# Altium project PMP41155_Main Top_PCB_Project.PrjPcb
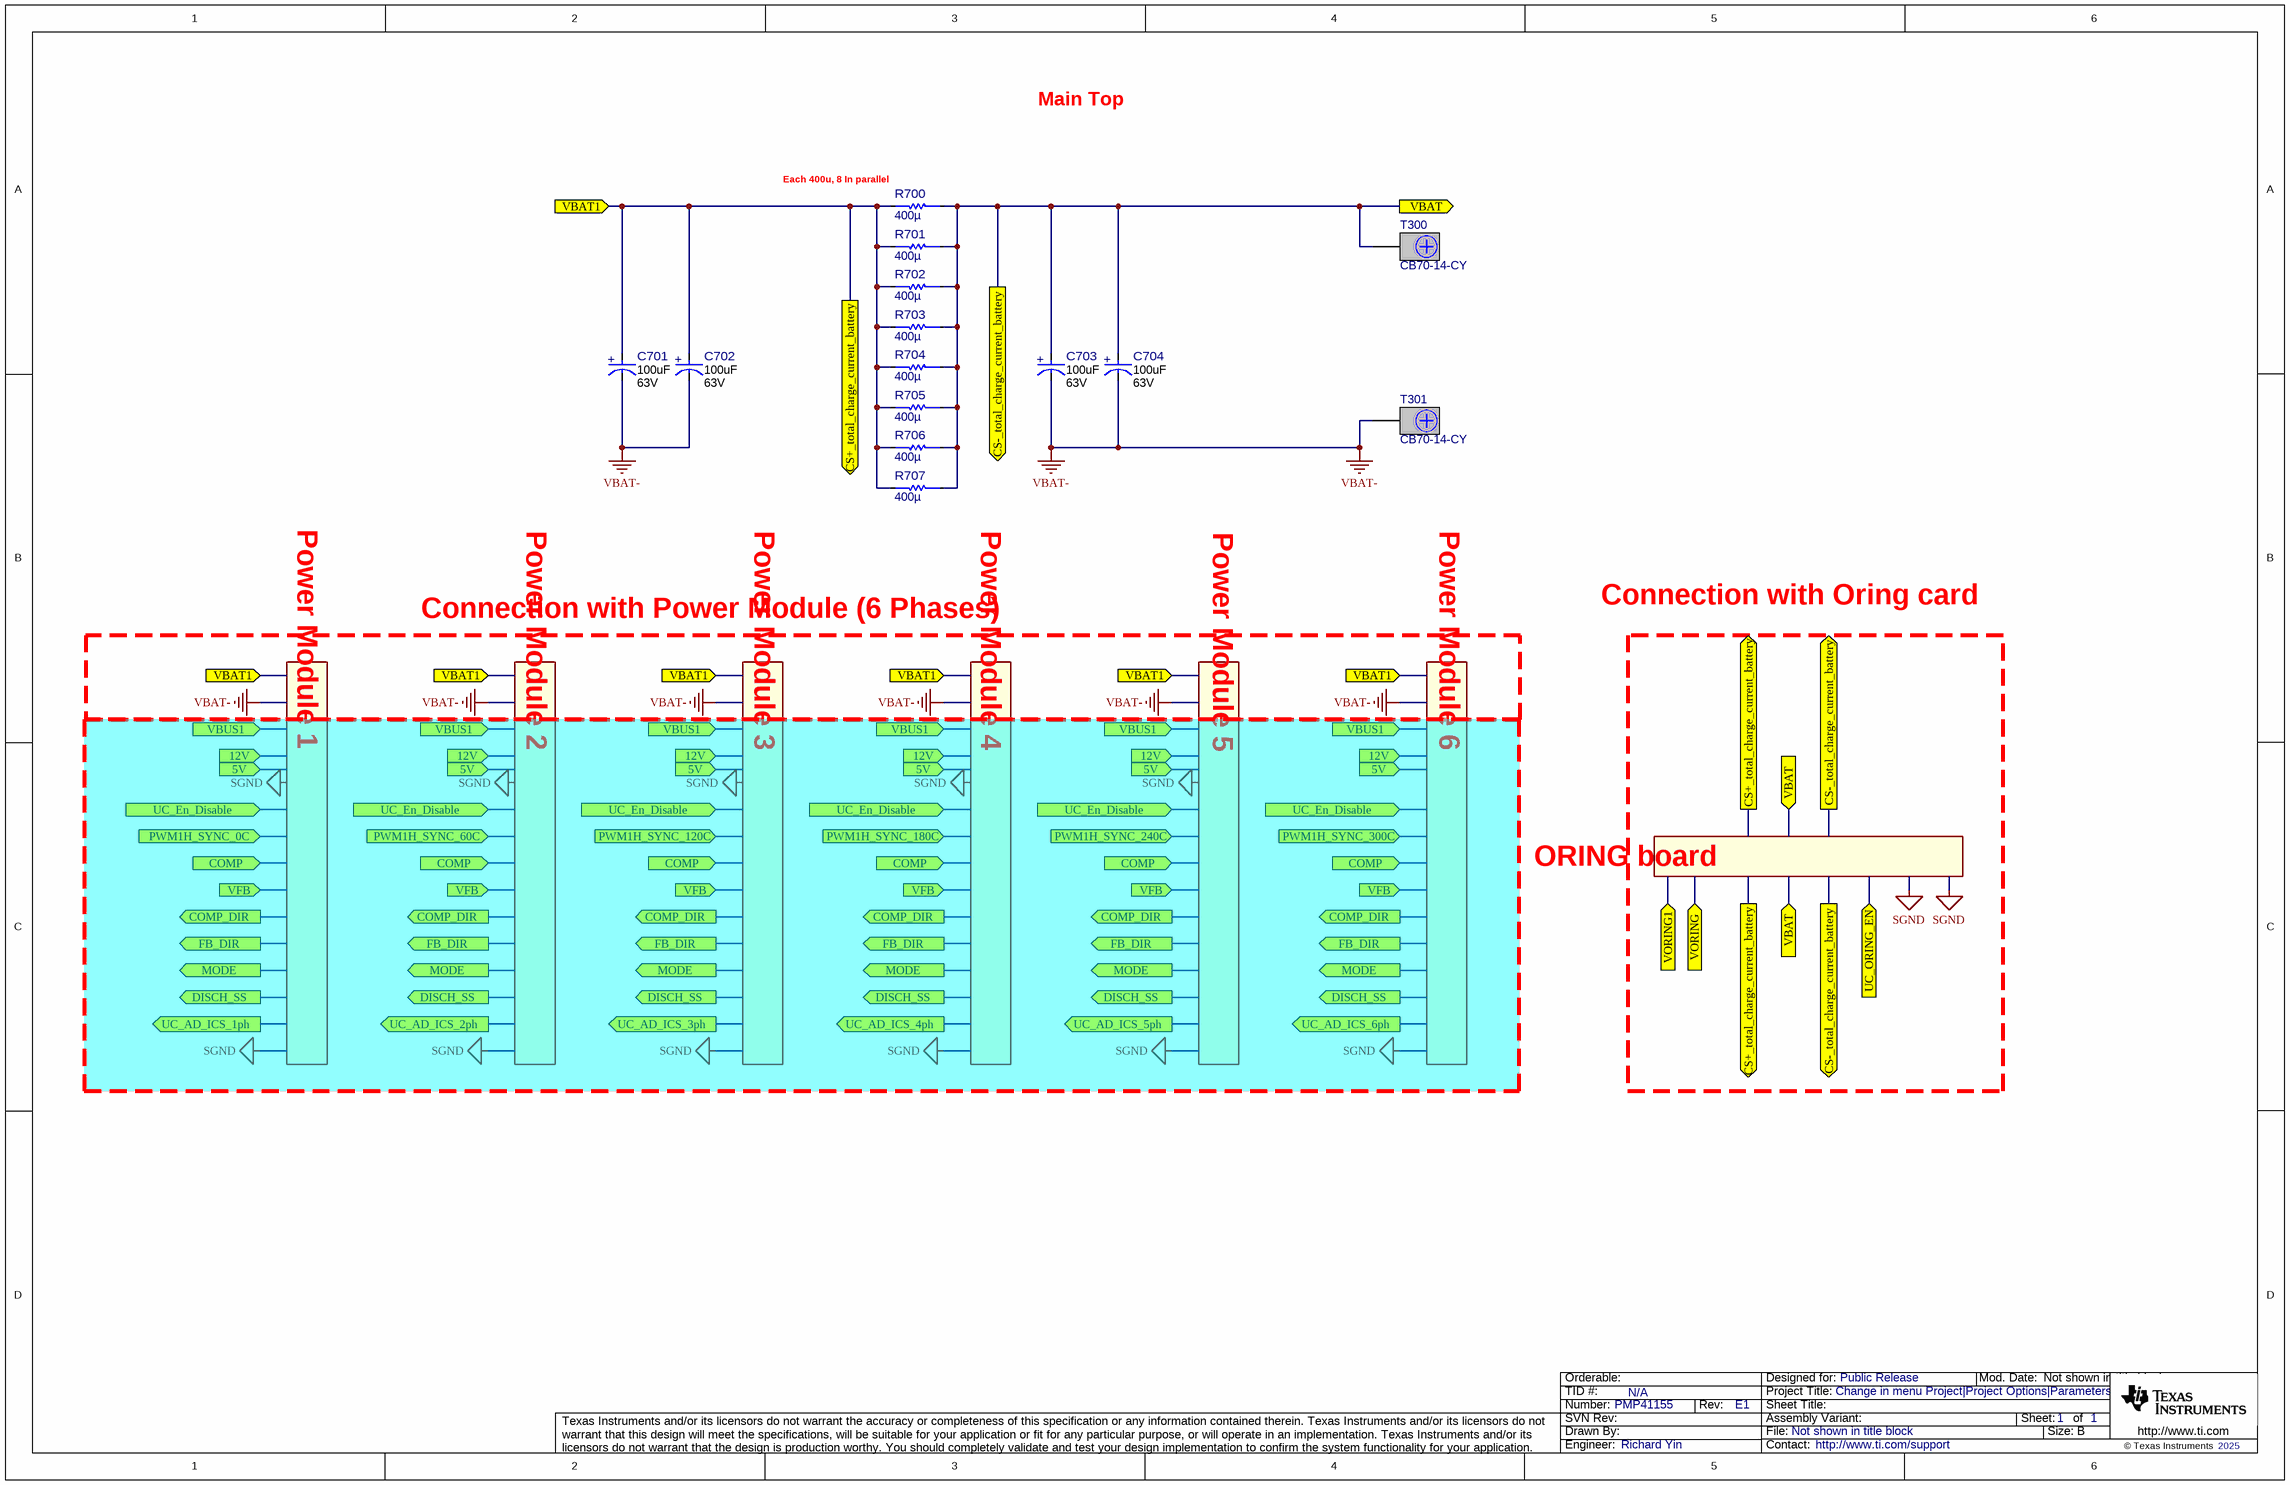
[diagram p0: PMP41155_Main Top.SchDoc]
CopyrightYear: 2025; PCB_Layout: Richard Yin; PCB_Rev: E1; PRJ_Customer: Public Release; PRJ_Engineer: Richard Yin; PRJ_Number: PMP41155; PRJ_Title: Change in menu Project|Project Options|Parameters; SCH_Rev: E1; TechSupport: http://www.ti.com/support; TID: N/A
1 sheet, 14 parts. Net scope: flat (ports and power ports of the same name join across sheets).
Board file: PMP41155_Main Top.PcbDoc

## Sheet PMP41155_Main Top.SchDoc
size 431 x 279 mm; Date: Not shown in title block; ApprovedBy: Not shown in title block; CheckedBy: Not shown in title block; Author: Not shown in title block; CompanyName: Not shown in title block; Engineer: Not shown in title block; Organization: Not shown in title block; Address1: Not shown in title block; Address2: Not shown in title block; Address3: Not shown in title block; Address4: Not shown in title block; DocumentNumber: 1; Revision: Use project parameter SCH_Rev; SheetNumber: 1; SheetTotal: 1; PageSetup: Record=PageOptions¦CenterHorizontal=True¦CenterVertical=True¦PrintScale=1.00¦XCorrection=1.00¦YCorrection=1.00¦PrintKind=0¦BorderSize=5000000¦LeftOffset=0¦BottomOffset=0¦Orientation=2¦PaperLength=1000¦PaperWidth=1000¦Scale=100¦PaperSource=15¦PrintQuality=600¦MediaType=1¦DitherType=10¦PaperKind=Letter¦PrintScaleMode=1

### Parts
C701  ValueDisplayed: 100uF  VDC_V: 63V  [FP-A769MS107M1JLAS018_RADIAL-MFG]  (hidden comment: A769MS107M1JLAS018)
C702  ValueDisplayed: 100uF  VDC_V: 63V  [FP-A769MS107M1JLAS018_RADIAL-MFG]  (hidden comment: A769MS107M1JLAS018)
C703  ValueDisplayed: 100uF  VDC_V: 63V  [FP-A769MS107M1JLAS018_RADIAL-MFG]  (hidden comment: A769MS107M1JLAS018)
C704  ValueDisplayed: 100uF  VDC_V: 63V  [FP-A769MS107M1JLAS018_RADIAL-MFG]  (hidden comment: A769MS107M1JLAS018)
R700  value 400µ  [FP-PU3921FKNP90U4L_3921-MFG]  (hidden comment: PU3921FKNP90U4L)
R701  value 400µ  [FP-PU3921FKNP90U4L_3921-MFG]  (hidden comment: PU3921FKNP90U4L)
R702  value 400µ  [FP-PU3921FKNP90U4L_3921-MFG]  (hidden comment: PU3921FKNP90U4L)
R703  value 400µ  [FP-PU3921FKNP90U4L_3921-MFG]  (hidden comment: PU3921FKNP90U4L)
R704  value 400µ  [FP-PU3921FKNP90U4L_3921-MFG]  (hidden comment: PU3921FKNP90U4L)
R705  value 400µ  [FP-PU3921FKNP90U4L_3921-MFG]  (hidden comment: PU3921FKNP90U4L)
R706  value 400µ  [FP-PU3921FKNP90U4L_3921-MFG]  (hidden comment: PU3921FKNP90U4L)
R707  value 400µ  [FP-PU3921FKNP90U4L_3921-MFG]  (hidden comment: PU3921FKNP90U4L)
T300  CB70-14-CY  [CB70-14-CY]
T301  CB70-14-CY  [CB70-14-CY]

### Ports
5V (in), 12V (in), COMP (in), COMP_DIR (out), CS+_total_charge_current_battery (out), CS-_total_charge_current_battery (out), DISCH_SS (out), FB_DIR (out), MODE (out), PWM1H_SYNC_0C (in), PWM1H_SYNC_60C (in), PWM1H_SYNC_120C (in), PWM1H_SYNC_180C (in), PWM1H_SYNC_240C (in), PWM1H_SYNC_300C (in), UC_AD_ICS_1ph (out), UC_AD_ICS_2ph (out), UC_AD_ICS_3ph (out), UC_AD_ICS_4ph (out), UC_AD_ICS_5ph (out), UC_AD_ICS_6ph (out), UC_En_Disable (in), UC_ORING_EN (in), VBAT1 (in), VBAT (in), VBAT (out), VBUS1 (in), VFB (in), VORING1 (in), VORING (in)

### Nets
VBAT-: C701.1(CATHODE) C702.1(CATHODE) C703.1(CATHODE) C704.1(CATHODE) T301.1
CS+_total_charge_current_battery: C701.2(ANODE) C702.2(ANODE) R700.2 R701.2 R702.2 R703.2 R704.2 R705.2 R706.2 R707.2 ; port VBAT1, port CS+_total_charge_current_battery
CS-_total_charge_current_battery: C703.2(ANODE) C704.2(ANODE) R700.1 R701.1 R702.1 R703.1 R704.1 R705.1 R706.1 R707.1 T300.1 ; port VBAT, port CS-_total_charge_current_battery

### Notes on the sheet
- Main Top
- (near R700) Each 400u, 8 In parallel
- Connection with Power Module (6 Phases)
- Connection with Oring card
- Power Module 1
- Power Module 2
- Power Module 3
- Power Module 4
- Power Module 5
- Power Module 6
- ORING board
- Labels drawn without touching a wire or pin: SGND

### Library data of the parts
C701-C704 = CMP-0040749-1: 100 µF 63 V Aluminum - Polymer Capacitors Radial, Can - SMD 2000 Hrs @ 125°C; Manufacturer: KEMET; AEC Grade: Grade 1; AEC Qualified: Yes; Cap_F: 100µF; IRMS_A: 2.7A; SizeZ_mm: 12.7mm; Tolerance_%: 20%; Esr: 18m; Leakage Current: 1260uA; Life: 2000Hours; Value: 100µF
R700-R707 = CMP-0096319-1: 400 µOhms ±1% 9W Chip Resistor Nonstandard Automotive AEC-Q200, Current Sense, Moisture Resistant Metal Element; Manufacturer: YAGEO; AEC Qualified: Yes; TempCo: 175ppm/°C; SizeZ_mm: 1.81mm; AEC Grade: Grade 0; Standoff Height: 0.37mm
T300 T301 = CMP-0055443-2: Terminal 90A Lug; Manufacturer: Panduit; Green_Lifecycle: Not Set; Cert_CULUS: Y; Green_REACh: Incomplete; Voltage_V: 600V; CompType: Screw Terminal; ContactFinish: Copper

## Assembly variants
001: all parts fitted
